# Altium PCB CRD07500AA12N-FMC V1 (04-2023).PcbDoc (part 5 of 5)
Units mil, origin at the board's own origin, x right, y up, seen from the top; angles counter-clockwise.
Board outline 8000 x 8000 mil, 4 copper layers (Top Layer, Layer 1, Layer 2, Bottom Layer), stack 107.988 mil thick; 393 components, 213 nets, 1142 pads, 380 vias.
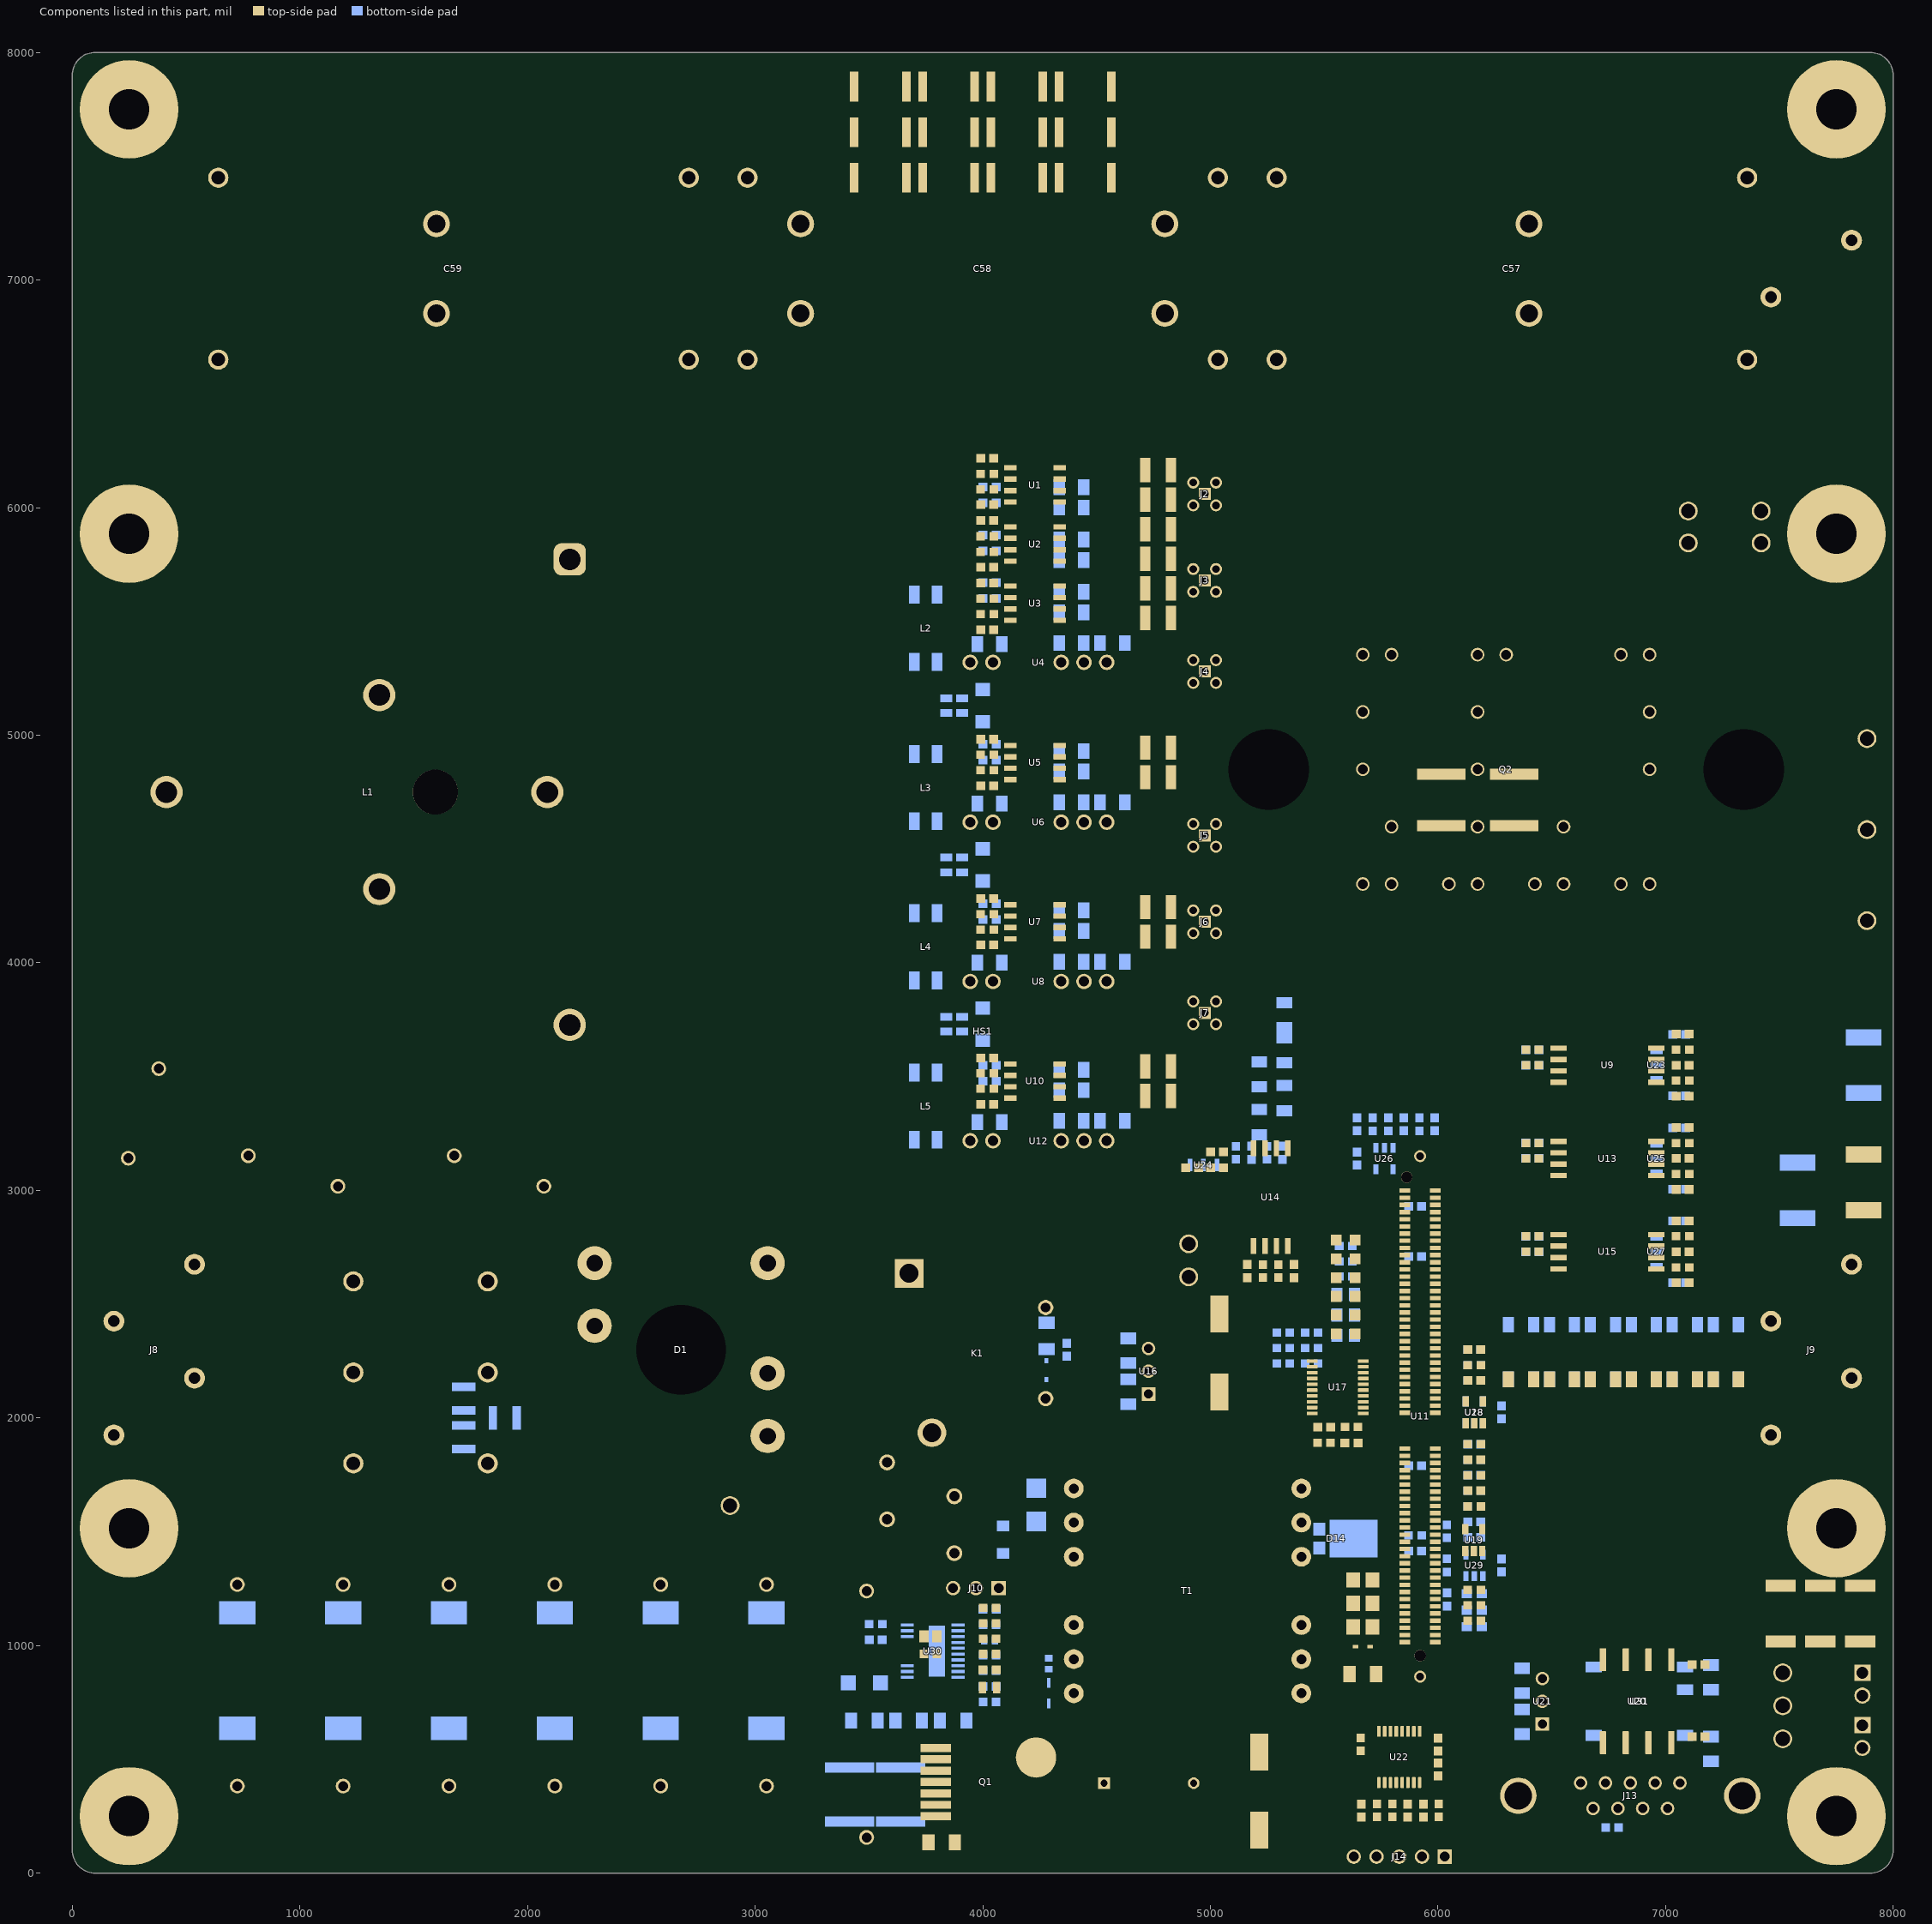
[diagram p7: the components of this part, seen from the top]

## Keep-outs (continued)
Layer 1:
  lines w10: 95,2400 ccw(c145,2400) 145,2350 ; 95,2470 cw(c145,2470) 145,2520 ; 315,3495 ccw(c365,3495) 365,3445 ; 315,3565 cw(c365,3565) 365,3615 ; 450,2140 ccw(c500,2140) 500,2090 ; 450,2210 cw(c500,2210) 500,2260 ; 450,2660 ccw(c500,2660) 500,2610 ; 450,2730 cw(c500,2730) 500,2780 ; 665,374.17 ccw(c715,374.17) 715,324.17 ; 665,389.17 cw(c715,389.17) 715,439.17 ; 1100,1240 ccw(c1150,1240) 1150,1190 ; 1230,1190 ccw(c1230,1240) 1280,1240 ; 1260,4260 ccw(c1310,4260) 1310,4210 ; 1260,4380 cw(c1310,4380) 1310,4430 ; 1270,1715 ccw(c1270,1765) 1320,1765 ; 1270,1885 cw(c1270,1835) 1320,1835 ; 1270,2115 ccw(c1270,2165) 1320,2165 ; 1270,2285 cw(c1270,2235) 1320,2235 ; 1270,2515 ccw(c1270,2565) 1320,2565 ; 1270,2685 cw(c1270,2635) 1320,2635 ; 1385,5270 cw(c1385,5220) 1435,5220 ; 1665,325 ccw(c1665,375) 1715,375 ; 1665,440 cw(c1665,390) 1715,390 ; 1735,2165 ccw(c1785,2165) 1785,2115 ; 1735,2205 cw(c1785,2205) 1785,2255 ; 1754.29,2525 ccw(c1789.64,2560.36) 1825,2525 ; 1864.36,2561.64 ccw(c1829,2597) 1864.36,2632.36 ; 1990,4805 cw(c2040,4805) 2040,4855 ; 2340,2320 ccw(c2340,2370) 2390,2370 ; 2340,2480 cw(c2340,2430) 2390,2430 ; 2960,1255 ccw(c3010,1255) 3010,1205 ; 2960,2165 ccw(c3010,2165) 3010,2115 ; 3090,1205 ccw(c3090,1255) 3140,1255 ; 3125,2115 ccw(c3125,2165) 3175,2165 ; 3210,2595 cw(c3210,2545) 3260,2545 ; 3430,365 ccw(c3480,365) 3480,315 ; 3430,1255 cw(c3480,1255) 3480,1305 ; 3515,2695 cw(c3565,2695) 3565,2745 ; 3648,95 ccw(c3698,95) 3698,45 ; 4110,6245 cw(c4110,6195) 4160,6195 ; 4180,1760 cw(c4180,1710) 4230,1710 ; 4225,2075 ccw(c4275,2075) 4275,2025 ; 4230,1540 ccw(c4280,1540) 4280,1490 ; 4305,6175 cw(c4355,6175) 4355,6225 ; 4415,1492 cw(c4415,1442) 4465,1442 ; 4420,45 ccw(c4420,95) 4470,95 ; 4465,495 ccw(c4515,495) 4515,445 ; 4470,295 cw(c4520,295) 4520,345 ccw(c4520,395) 4570,395 ccw(c4520,395) 4520,445 ; 4945,345 cw(c4945,395) 4895,395 cw(c4945,395) 4945,445 ; 5105,6225 cw(c5105,6175) 5155,6175 ; 5110,345 cw(c5110,295) 5160,295 ; 5110,445 ccw(c5110,495) 5160,495 ; 5160,95 ccw(c5210,95) 5210,45 ; 5160,600 cw(c5210,600) 5210,650 ; 5285,650 ccw(c5285,700) 5335,700 ; 5285,2025 cw(c5285,1975) 5335,1975 ; 5385,5640 ccw(c5435,5640) 5435,5590 ; 5385,5660 cw(c5435,5660) 5435,5710 ; 5570,2885 ccw(c5570,2935) 5620,2935 ; 5620,3335 cw(c5670,3335) 5670,3385 ; 6015,3385 ccw(c6015,3435) 6065,3435 ; 6065,3620 cw(c6115,3620) 6115,3670 ; 6115,45 ccw(c6115,95) 6165,95 ; 6165,530 cw(c6215,530) 6215,580 ; 6175,4385 cw(c6175,4335) 6225,4335 ; 6290,295 ccw(c6340,295) 6340,245 ; 6290,395 cw(c6340,395) 6340,445 ; 6340,1125 ccw(c6390,1125) 6390,1075 ; 6340,2550 cw(c6390,2550) 6390,2600 ; 6355,4020 ccw(c6355,4040) 6375,4040 ; 6355,4080 cw(c6355,4060) 6375,4060 ; 6450,580 ccw(c6450,630) 6500,630 ; 6500,810 cw(c6550,810) 6550,860 ; 6525,2600 ccw(c6525,2650) 6575,2650 ; 6525,3670 cw(c6525,3620) 6575,3620 ; 6550,4385 cw(c6550,4335) 6600,4335 ; 6590,445 ccw(c6590,495) 6640,495 ; 6610.55,3959.71 ccw(c6660.36,3955.36) 6625,3920 ; 6640,585 cw(c6690,585) 6690,635 ; 6900,4005 ccw(c6930,4005) 6930,3975 ; 6900,4050 cw(c6930,4050) 6930,4080 ; 6915,4385 cw(c6915,4335) 6965,4335 ; 6925,5500 cw(c6925,5450) 6975,5450 ; 6997,860 cw(c6997,810) 7047,810 ; 7045,825 ccw(c7095,825) 7095,775 ; 7148.79,4008.79 cw(c7170,4030) 7148.79,4051.21 ; 7178.79,4081.21 cw(c7200,4060) 7221.21,4081.21 ; 7190,635 cw(c7190,585) 7240,585 ; 7190,775 ccw(c7190,825) 7240,825 ; 7240,495 ccw(c7290,495) 7290,445 ; 7240,815 cw(c7290,815) 7290,865 ; 7350,245 ccw(c7350,295) 7400,295 ; 7350,445 cw(c7350,395) 7400,395 ; 7410,1245 ccw(c7460,1245) 7460,1195 ; 7410,1950 cw(c7460,1950) 7460,2000 ; 7415,860 cw(c7415,810) 7465,810 ; 7465,555 ccw(c7515,555) 7515,505 ; 7570,3200 ccw(c7620,3200) 7620,3150 ; 7700,3150 ccw(c7700,3200) 7750,3200 ; 7900,505 ccw(c7900,555) 7950,555 ; 7900,1075 cw(c7900,1025) 7950,1025 ; 7900,1195 ccw(c7900,1245) 7950,1245 ; 7900,2000 cw(c7900,1950) 7950,1950
Layer 2:
  region: 6463.94,5460 6408.94,5460 6408.94,5245 6463.94,5245
  region: 6278.94,4745 6068.94,4745 6068.94,4690 6278.94,4690
  region: 5960,5460 5905,5460 5905,5245 5960,5245
  region: 5775,4745 5565,4745 5565,4690 5775,4690
  rectangle: 6825,4690 7035,4745
  rectangle: 6640,5245 6695,5460
  region: 6069.93,5515 6013.94,5459.01 6013.94,5190 6013.94,4955 6013.94,4745 6334.02,4745 6334.02,4955 6334.02,5190 6408.94,5190 6408.94,5515
  region: 5566,5515 5510,5459.01 5510,5190 5510,4955 5510,4745 5830.08,4745 5830.08,4955 5830.08,5190 5905,5190 5905,5515
  region: 7034,5515 7090,5459.01 7090,5190 7090,4955 7090,4745 6769.92,4745 6769.92,4955 6769.92,5190 6695,5190 6695,5515
  lines w10: 165,3100 ccw(c215,3100) 215,3050 ; 165,3185 cw(c215,3185) 215,3235 ; 205,4845 cw(c255,4845) 255,4895 ; 530,4895 cw(c530,4845) 580,4845 ; 594.21,6215 ccw(c644.21,6215) 644.21,6165 ; 595,6430.79 cw(c645,6430.79) 645,6480.79 ; 595,6870.79 ccw(c645,6870.79) 645,6820.79 ; 595,7230 cw(c645,7230) 645,7280 ; 595,7670 ccw(c645,7670) 645,7620 ; 595,7875 cw(c645,7875) 645,7925 ; 635,1110 ccw(c685,1110) 685,1060 ; 635,1720 cw(c685,1720) 685,1770 ; 650,3235 ccw(c650,3285) 700,3285 ; 700,1770 ccw(c700,1820) 750,1820 ; 700,3050 cw(c700,3000) 750,3000 ; 765,1060 ccw(c765,1110) 815,1110 ; 815,1465 cw(c865,1465) 865,1515 ; 1100,3025 ccw(c1150,3025) 1150,2975 ; 1100,3070 cw(c1150,3070) 1150,3120 ; 1440,2975 cw(c1440,2925) 1490,2925 ; 1440,3120 ccw(c1440,3170) 1490,3170 ; 1490,2165 ccw(c1540,2165) 1540,2115 ; 1565,1110 ccw(c1615,1110) 1615,1060 ; 1610,1665 ccw(c1610,1715) 1660,1715 ; 1660,1805 cw(c1710,1805) 1710,1855 ; 1680,2305 ccw(c1730,2305) 1730,2255 ; 1695,1060 ccw(c1695,1110) 1745,1110 ; 1825,2255 cw(c1825,2205) 1875,2205 ; 1830,1515 ccw(c1830,1565) 1880,1565 ; 1830,1855 cw(c1830,1805) 1880,1805 ; 2040,5910 cw(c2090,5910) 2090,5960 ; 2190,2655 ccw(c2240,2655) 2240,2605 ; 2235,3830 cw(c2235,3780) 2285,3780 ; 2540,5960 cw(c2540,5910) 2590,5910 ; 2730,6165 cw(c2730,6115) 2780,6115 ; 2805,2605 ccw(c2805,2655) 2855,2655 ; 2845,6770 3060,6975 ; 2880,7305 3110,7125 ; 3075,6520 3305,6700 ; 3095,7555 3310,7350 ; 3210,140 ccw(c3260,140) 3260,90 ; 3435,330 ccw(c3485,330) 3485,280 ; 3570,90 ccw(c3570,140) 3620,140 ; 3570,280 cw(c3570,230) 3620,230 ; 4225,2075 ccw(c4275,2075) 4275,2025 ; 4405,1600 ccw(c4405,1650) 4455,1650 ; 4405,1790 cw(c4405,1740) 4455,1740 ; 5015,2885 cw(c5015,2835) 5065,2835 cw(c5115,2835) 5115,2885 ; 5065,2620 ccw(c5115,2620) 5115,2570 ; 5130.79,6365 cw(c5130.79,6315) 5180.79,6315 ; 5160,95 ccw(c5210,95) 5210,45 ; 5160,600 cw(c5210,600) 5210,650 ; 5180,5107 ccw(c5230,5107) 5230,5057 ; 5285,650 ccw(c5285,700) 5335,700 ; 5285,2025 cw(c5285,1975) 5335,1975 ; 5400,2570 ccw(c5400,2620) 5450,2620 ; 5450,2740 cw(c5500,2740) 5500,2790 ; 5465,4610 ccw(c5515,4610) 5515,4560 ; 5515,4745 ccw(c5565,4745) 5565,4695 ; 5515,5460 cw(c5565,5460) 5565,5510 ; 5570,2885 ccw(c5570,2935) 5620,2935 ; 5620,3335 cw(c5670,3335) 5670,3385 ; 5735,2790 ccw(c5735,2840) 5785,2840 ; 5775,4695 ccw(c5775,4745) 5825,4745 ; 5785,3015 cw(c5835,3015) 5835,3065 ; 5825,5145 cw(c5875,5145) 5875,5195 ; 5905,5195 ccw(c5905,5245) 5955,5245 ; 5905,5510 cw(c5905,5460) 5955,5460 ; 6015,3065 cw(c6015,3015) 6065,3015 ; 6015,3385 ccw(c6015,3435) 6065,3435 ; 6018.94,4745 ccw(c6068.94,4745) 6068.94,4695 ; 6018.94,5460 cw(c6068.94,5460) 6068.94,5510 ; 6020,1005 ccw(c6070,1005) 6070,955 ; 6020,1010 ccw(c6070,1010) 6070,960 ; 6065,3620 cw(c6115,3620) 6115,3670 ; 6115,45 ccw(c6115,95) 6165,95 ; 6165,530 cw(c6215,530) 6215,580 ; 6278.94,4695 ccw(c6278.94,4745) 6328.94,4745 ; 6290,960 ccw(c6290,1010) 6340,1010 ; 6295,955 ccw(c6295,1005) 6345,1005 ; 6328.94,5145 cw(c6378.94,5145) 6378.94,5195 ; 6340,2550 cw(c6390,2550) 6390,2600 ; 6345,1025 cw(c6395,1025) 6395,1075 ; 6408.94,5195 ccw(c6408.94,5245) 6458.94,5245 ; 6408.94,5510 cw(c6408.94,5460) 6458.94,5460 ; 6440,295 ccw(c6490,295) 6490,245 ; 6440,395 cw(c6490,395) 6490,445 ; 6450,580 ccw(c6450,630) 6500,630 ; 6525,2600 ccw(c6525,2650) 6575,2650 ; 6525,3670 cw(c6525,3620) 6575,3620 ; 6640,585 cw(c6690,585) 6690,635 ; 6645,5245 ccw(c6695,5245) 6695,5195 ; 6645,5460 cw(c6695,5460) 6695,5510 ; 6725,5195 cw(c6725,5145) 6775,5145 ; 6775,4745 ccw(c6825,4745) 6825,4695 ; 6997,860 cw(c6997,810) 7047,810 ; 7035,4695 ccw(c7035,4745) 7085,4745 ; 7035,5510 cw(c7035,5460) 7085,5460 ; 7045,825 ccw(c7095,825) 7095,775 ; 7085,4560 ccw(c7085,4610) 7135,4610 ; 7190,245 ccw(c7190,295) 7240,295 ; 7190,635 cw(c7190,585) 7240,585 ; 7190,775 ccw(c7190,825) 7240,825 ; 7240,815 cw(c7290,815) 7290,865 ; 7240,5715 ccw(c7290,5715) 7290,5665 ; 7240,6105 cw(c7290,6105) 7290,6155 ; 7320,7925 cw(c7320,7875) 7370,7875 ; 7370,7560 ccw(c7420,7560) 7420,7510 ; 7410,1245 ccw(c7460,1245) 7460,1195 ; 7410,1950 cw(c7460,1950) 7460,2000 ; 7415,860 cw(c7415,810) 7465,810 ; 7420,5057 ccw(c7420,5107) 7470,5107 ; 7420,5665 cw(c7420,5615) 7470,5615 ; 7465,555 ccw(c7515,555) 7515,505 ; 7480,6155 ccw(c7480,6205) 7530,6205 ; 7480,7510 cw(c7480,7460) 7530,7460 ; 7900,505 ccw(c7900,555) 7950,555 ; 7900,1195 ccw(c7900,1245) 7950,1245 ; 7900,2000 cw(c7900,1950) 7950,1950
  lines w100: 2885,6735 3100,6940 ; 2915,7345 3145,7165 ; 3040,6560 3270,6740 ; 3055,7520 3270,7315
Bottom Layer:
  region: 7262,5995 7242,5995 7242,5820 7262,5820
  rectangle: 6918,5820 6938,5995
  lines w10: 20,595 ccw(c70,595) 70,545 ; 20,1930 cw(c70,1930) 70,1980 ; 165,3100 ccw(c215,3100) 215,3050 ; 165,3185 cw(c215,3185) 215,3235 ; 205,4845 cw(c255,4845) 255,4895 ; 395,775 ccw(c445,775) 445,725 ; 420,1980 cw(c420,1930) 470,1930 ; 530,4895 cw(c530,4845) 580,4845 ; 530,6215 ccw(c580,6215) 580,6165 ; 530,7875 cw(c580,7875) 580,7925 ; 635,1110 ccw(c685,1110) 685,1060 ; 635,1720 cw(c685,1720) 685,1770 ; 650,3235 ccw(c650,3285) 700,3285 ; 700,1770 ccw(c700,1820) 750,1820 ; 700,3050 cw(c700,3000) 750,3000 ; 765,1060 ccw(c765,1110) 815,1110 ; 815,1465 cw(c865,1465) 865,1515 ; 1100,1110 ccw(c1150,1110) 1150,1060 ; 1100,1285 cw(c1150,1285) 1150,1335 ; 1100,3025 ccw(c1150,3025) 1150,2975 ; 1100,3070 cw(c1150,3070) 1150,3120 ; 1230,1060 ccw(c1230,1110) 1280,1110 ; 1230,1335 cw(c1230,1285) 1280,1285 ; 1440,2975 cw(c1440,2925) 1490,2925 ; 1440,3120 ccw(c1440,3170) 1490,3170 ; 1465,1965 ccw(c1490,1965) 1490,1940 ; 1465,1975 cw(c1490,1975) 1490,2000 ; 1490,2165 ccw(c1540,2165) 1540,2115 ; 1565,1110 ccw(c1615,1110) 1615,1060 ; 1610,1665 ccw(c1610,1715) 1660,1715 ; 1680,2305 ccw(c1730,2305) 1730,2255 ; 1695,1060 ccw(c1695,1110) 1745,1110 ; 1825,2255 cw(c1825,2205) 1875,2205 ; 1830,1515 ccw(c1830,1565) 1880,1565 ; 1830,1855 cw(c1830,1805) 1880,1805 ; 2030,1110 ccw(c2080,1110) 2080,1060 ; 2040,5910 cw(c2090,5910) 2090,5960 ; 2160,1060 ccw(c2160,1110) 2210,1110 ; 2200,2430 cw(c2250,2430) 2250,2480 ; 2235,3830 cw(c2235,3780) 2285,3780 ; 2340,2480 cw(c2340,2430) 2390,2430 ; 2495,1110 ccw(c2545,1110) 2545,1060 ; 2540,5960 cw(c2540,5910) 2590,5910 ; 2555,2596 ccw(c2605,2596) 2605,2546 ; 2625,1060 ccw(c2625,1110) 2675,1110 ; 2730,6165 cw(c2730,6115) 2780,6115 ; 2894.68,2413.87 ccw(c2940,2435) 2940,2385 ; 2960,1110 ccw(c3010,1110) 3010,1060 ; 2960,1285 cw(c3010,1285) 3010,1335 ; 3090,1060 ccw(c3090,1110) 3140,1110 ; 3090,1335 cw(c3090,1285) 3140,1285 ; 3095,545 ccw(c3095,595) 3145,595 ; 3095,725 cw(c3095,675) 3145,675 ; 3100,2095 ccw(c3100,2145) 3150,2145 ; 3100,2295 cw(c3100,2245) 3150,2245 ; 3215,2385 cw(c3215,2335) 3265,2335 ; 3265,1250 ccw(c3315,1250) 3315,1200 ; 3300,170 ccw(c3350,170) 3350,120 ; 3325,675 ccw(c3375,675) 3375,625 ; 3325,830 cw(c3375,830) 3375,880 ; 3400,880 cw(c3400,830) 3450,830 ; 3485,1200 ccw(c3485,1250) 3535,1250 ; 3485,2795 ccw(c3535,2795) 3535,2745 ; 3535,1460 cw(c3585,1460) 3585,1510 ccw(c3585,1560) 3635,1560 ; 3535,1650 ccw(c3585,1650) 3585,1600 cw(c3585,1550) 3635,1550 ; 3535,2450 cw(c3585,2450) 3585,2500 ; 3705,120 ccw(c3705,170) 3755,170 ; 3719,2500 ccw(c3719,2550) 3769,2550 ; 3720,2744 cw(c3720,2694) 3770,2694 ; 3820,1405 ccw(c3870,1405) 3870,1355 ; 3820,1655 cw(c3870,1655) 3870,1705 ; 3880,1355 ccw(c3880,1405) 3930,1405 ; 3880,1705 cw(c3880,1655) 3930,1655 ; 4225,2075 ccw(c4275,2075) 4275,2025 ; 4687.5,7347.5 4902.5,7552.5 ; 4690,6705 4920,6525 ; 4890,7125 5120,7305 ; 4935,6980 5150,6775 ; 5005,6195 cw(c5005,6145) 5055,6145 ; 5045,6310 cw(c5045,6260) 5095,6260 ; 5050,2885 cw(c5050,2835) 5100,2835 ; 5095,5128 ccw(c5145,5128) 5145,5078 ; 5100,2210 ccw(c5150,2210) 5150,2160 ; 5100,2450 cw(c5150,2450) 5150,2500 ; 5100,2630 ccw(c5150,2630) 5150,2580 ; 5160,95 ccw(c5210,95) 5210,45 ; 5160,600 cw(c5210,600) 5210,650 ; 5285,650 ccw(c5285,700) 5335,700 ; 5285,2025 cw(c5285,1975) 5335,1975 ; 5335,1285 cw(c5385,1285) 5385,1335 cw(c5385,1385) 5335,1385 ; 5335,1555 cw(c5385,1555) 5385,1605 cw(c5385,1655) 5335,1655 ; 5375,5660 cw(c5425,5660) 5425,5710 ; 5460,1335 ccw(c5460,1385) 5510,1385 ; 5460,1605 cw(c5460,1555) 5510,1555 ; 5485,4805 ccw(c5535,4805) 5535,4755 ; 5500,5710 cw(c5500,5660) 5550,5660 ; 5580,2160 cw(c5580,2110) 5630,2110 ; 5630,1650 ccw(c5680,1650) 5680,1600 ; 5685,5025 ccw(c5685,5075) 5735,5075 ; 5685,5230 cw(c5685,5180) 5735,5180 ; 5690,1600 cw(c5690,1550) 5740,1550 ; 5740,1060 ccw(c5790,1060) 5790,1010 ; 6005,4215 ccw(c6055,4215) 6055,4165 ; 6115,45 ccw(c6115,95) 6165,95 ; 6165,530 cw(c6215,530) 6215,580 ; 6175,4385 cw(c6175,4335) 6225,4335 ; 6225,4275 ccw(c6275,4275) 6275,4225 ; 6290,295 ccw(c6340,295) 6340,245 ; 6290,395 cw(c6340,395) 6340,445 ; 6295,4020 cw(c6295,4050) 6265,4050 cw(c6295,4050) 6295,4080 ; 6450,580 ccw(c6450,630) 6500,630 ; 6590,445 ccw(c6590,495) 6640,495 ; 6870,4020 cw(c6870,3990) 6900,3990 ; 6900,3995 ccw(c6920,3995) 6920,3975 ; 6920,1025 cw(c6970,1025) 6970,1075 ; 6945,4080 cw(c6945,4050) 6975,4050 ; 6955,3975 ccw(c6955,3995) 6975,3995 ; 7066,4755 ccw(c7066,4805) 7116,4805 ; 7177.14,3982.14 ccw(c7212.5,4017.5) 7247.86,3982.14 ; 7190,635 cw(c7190,585) 7240,585 ; 7240,495 ccw(c7290,495) 7290,445 ; 7250.47,3984.64 ccw(c7215.12,4020) 7250.47,4055.36 ; 7268.02,6793.8 ccw(c7243.02,6837.1) 7290,6820 ; 7290,7045 cw(c7340,7045) 7340,7095 ; 7350,245 ccw(c7350,295) 7400,295 ; 7350,445 cw(c7350,395) 7400,395 ; 7410,1245 ccw(c7460,1245) 7460,1195 ; 7410,1950 cw(c7460,1950) 7460,2000 ; 7420,5077 ccw(c7420,5127) 7470,5127 ; 7420,6481 cw(c7420,6431) 7470,6431 ; 7420,7619 ccw(c7420,7669) 7470,7669 ; 7420,7925 cw(c7420,7875) 7470,7875 ; 7465,555 ccw(c7515,555) 7515,505 ; 7570,5270 cw(c7620,5270) 7620,5320 ; 7730,2160 ccw(c7780,2160) 7780,2110 ; 7765,2660 ccw(c7815,2660) 7815,2610 ; 7830,7095 ccw(c7830,7145) 7880,7145 ; 7830,7280 cw(c7830,7230) 7880,7230 ; 7855,2110 ccw(c7855,2160) 7905,2160 ; 7900,505 ccw(c7900,555) 7950,555 ; 7900,1075 cw(c7900,1025) 7950,1025 ; 7900,1195 ccw(c7900,1245) 7950,1245 ; 7900,2000 cw(c7900,1950) 7950,1950 ; 7900,5320 cw(c7900,5270) 7950,5270 ; 7925,2610 ccw(c7925,2660) 7975,2660
  lines w100: 4725,6745 4955,6565 ; 4727.5,7312.5 4942.5,7517.5 ; 4855,7165 5085,7345 ; 4895,6945 5110,6740

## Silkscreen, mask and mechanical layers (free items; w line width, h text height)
Top Overlay:
  drawing of 52 lines, arcs and shapes, not listed
  text "DC-" at 7073.42,7125 h100
  text "DC+" at 7073.42,6870 h100
  text "7.5kW WolfPACK FM3 Six-Pack Motor Drive / PN CRD07500AA12N-FMC, V1 04/2023" at 2163.26,6255 h95
  text "H" at 831.25,6231.88 h900
  text "H" at 6531.25,6231.88 h900
  text "(ROFF)" at 4488.23,6126 h35
  text "(RON)" at 4523.21,5996 h35
  text "(ROFF)" at 4488.23,5866 h35
  text "U_L / (G2)" at 4913.6,5865 h35
  text "(RON)" at 4523.21,5736 h35
  text "DC+" at 7020.03,5705 h60
  text "DC-" at 7340.03,5705 h60
  text "(ROFF)" at 4488.23,5606 h35
  text "V_L / (G4)" at 4913.6,5485 h35
  text "(RON)" at 4523.21,5476 h35
  text "W_L / (G6)" at 4913.6,5085 h35
  text "U" at 7708.35,4945 h100
  text "(ROFF)" at 4488.23,4906 h35
  text "(RON)" at 4523.21,4776 h35
  text "V" at 7708.35,4545 h100
  text "W_H / (G5)" at 4913.6,4365 h35
  text "(ROFF)" at 4488.23,4206 h35
  text "W" at 7708.35,4145 h100
  text "(RON)" at 4523.21,4076 h35
  text "V_H / (G3)" at 4913.6,3985 h35
  text "U_H / (G1)" at 4913.6,3585 h35
  text "(ROFF)" at 4488.23,3506 h35
  text "(RON)" at 4523.21,3376 h35
  text "OUTPUTS" at 7560,2820 h125 r90
  text "+12V" at 4605.07,2735 h60
  text "INPUTS" at 795,2643.64 h125 r270
  text "A" at 670,2625 h100
  text "U" at 7273.35,2625 h100
  text "GND" at 4655.05,2590 h60
  text "+12V" at 5270.07,2504 h60
  text "+5V" at 5320.05,2422 h60
  text "B" at 670,2375 h100
  text "V" at 7273.35,2370 h100
  text "+3.3" at 5270.07,2340 h60
  text "C" at 670,2125 h100
  text "W" at 7273.35,2010 h100
  text "g" at 639.18,1741.09 h310
  text "g" at 7154.18,1741.09 h310
  text "BRIDGE-" at 2695.06,1475 h60
  text "EN" at 4174,1215.84 h35 r90
  text "DIS" at 3797.51,1204.51 h35 r90
  text "+" at 7680.01,905 h60
  text "GND" at 7265.05,850 h60
  text "-" at 7729.99,850.01 h60 r90
  text "+3.3V" at 7155.09,705 h60
  text "FAN" at 7720,635.05 h60 r90
  text "+5V" at 7265.05,560 h60
  text "+" at 7680.01,535 h60
  text "-" at 7729.99,480.01 h60 r90
  text "5" at 5460.67,161 h35
  text "GND" at 5523.35,161 h35
  text "+5V" at 5653.35,161 h35
  text "1I" at 5809.59,161 h35
  text "1B" at 5938.76,161 h35
  text "1A" at 6068.76,161 h35
  text "1" at 6176,161 h35
Bottom Overlay:
  lines w10: 3785,3730 3817.36,3730 ; 3785,4430 3817.36,4430 ; 3785,5130 3817.36,5130 ; 5445,2190 5445,2206.3 ; 6220,1285 6240,1265 6385,1265 ; 3665,3650 3785,3650 3785,3810 3665,3810 3665,3650 ; 3665,4350 3785,4350 3785,4510 3665,4510 3665,4350 ; 3665,5050 3785,5050 3785,5210 3665,5210 3665,5050 ; 5370,2020 5520,2020 5520,2190 5370,2190 5370,2020
Board Outline:
  the board outline again, w10
Drill Drawing:
  drawing of 191 lines, arcs and shapes, not listed
  text "THESE HOLES (1.10MM +/- 0.05MM) ARE FOR PRESS-FIT PART. USE 47.2MIL +/- 1MIL DRILLED HOLES. COPPER THICKNESS IN HOLE 25-50UM." at 250,12130 h100
  text "w" at 34.31,12114.72 h200
  text "Symbol" at 109.62,11935 h72
  text "Count" at 615.49,11935 h72
  text "Hole Size" at 1215.34,11935 h72
  text "Plated" at 2365,11935 h72
  text "Hole Type" at 2870.88,11935 h72
  text "Drill Layer Pair" at 3604.68,11935 h72
  text "Via/Pad" at 5104.23,11935 h72
  text "Pad Shape" at 5694.08,11935 h72
  text "Hole Tolerance (+)" at 6439.88,11935 h72
  text "Hole Tolerance (-)" at 7773.48,11935 h72
  text "Hole Length" at 9107.09,11935 h72
  text "Routed Path Length" at 9972.85,11935 h72
  text "367" at 615.49,11785 h60
  text "0.33mm (13.00mil)" at 1215.34,11785 h60
  text "PTH" at 2365,11785 h60
  text "Round" at 2870.88,11785 h60
  text "Top Layer - Bottom Layer" at 3604.68,11785 h60
  text "Via" at 5104.23,11785 h60
  text "Rounded" at 5694.08,11785 h60
  text "0.08mm (3.00mil)" at 6439.88,11785 h60
  text "0.08mm (3.00mil)" at 7773.48,11785 h60
  text "-" at 9107.09,11785 h60
  text "-" at 9972.85,11785 h60
  text "A" at 80.53,11775.01 h66.67
  text "13" at 615.49,11635 h60
  text "0.71mm (28.00mil)" at 1215.34,11635 h60
  text "PTH" at 2365,11635 h60
  text "Round" at 2870.88,11635 h60
  text "Top Layer - Bottom Layer" at 3604.68,11635 h60
  text "Via" at 5104.23,11635 h60
  text "Rounded" at 5694.08,11635 h60
  text "0.08mm (3.00mil)" at 6439.88,11635 h60
  text "0.08mm (3.00mil)" at 7773.48,11635 h60
  text "-" at 9107.09,11635 h60
  text "-" at 9972.85,11635 h60
  text "2" at 615.49,11485 h60
  text "0.80mm (31.50mil)" at 1215.34,11485 h60
  text "PTH" at 2365,11485 h60
  text "Round" at 2870.88,11485 h60
  text "Top Layer - Bottom Layer" at 3604.68,11485 h60
  text "Pad" at 5104.23,11485 h60
  text "(Mixed)" at 5694.08,11485 h60
  text "0.08mm (3.00mil)" at 6439.88,11485 h60
  text "0.08mm (3.00mil)" at 7773.48,11485 h60
  text "-" at 9107.09,11485 h60
  text "-" at 9972.85,11485 h60
  text "D" at 80.53,11475.01 h66.67
  text "32" at 615.49,11335 h60
  text "0.84mm (33.07mil)" at 1215.34,11335 h60
  text "PTH" at 2365,11335 h60
  text "Round" at 2870.88,11335 h60
  text "Top Layer - Bottom Layer" at 3604.68,11335 h60
  text "Pad" at 5104.23,11335 h60
  text "(Mixed)" at 5694.08,11335 h60
  text "0.08mm (3.00mil)" at 6439.88,11335 h60
  text "0.08mm (3.00mil)" at 7773.48,11335 h60
  text "-" at 9107.09,11335 h60
  text "-" at 9972.85,11335 h60
  text "15" at 615.49,11185 h60
  text "1.00mm (39.37mil)" at 1215.34,11185 h60
  text "PTH" at 2365,11185 h60
  text "Round" at 2870.88,11185 h60
  text "Top Layer - Bottom Layer" at 3604.68,11185 h60
  text "Pad" at 5104.23,11185 h60
  text "(Mixed)" at 5694.08,11185 h60
  text "0.08mm (3.00mil)" at 6439.88,11185 h60
  text "0.08mm (3.00mil)" at 7773.48,11185 h60
  text "-" at 9107.09,11185 h60
  text "-" at 9972.85,11185 h60
  text "23" at 615.49,11035 h60
  text "1.10mm (43.31mil)" at 1215.34,11035 h60
  text "PTH" at 2365,11035 h60
  text "Round" at 2870.88,11035 h60
  text "Top Layer - Bottom Layer" at 3604.68,11035 h60
  text "Pad" at 5104.23,11035 h60
  text "Rounded" at 5694.08,11035 h60
  text "0.05mm (1.97mil)" at 6439.88,11035 h60
  text "0.05mm (1.97mil)" at 7773.48,11035 h60
  text "-" at 9107.09,11035 h60
  text "-" at 9972.85,11035 h60
  text "w" at -180.69,10999.72 h200
  text "42" at 615.49,10885 h60
  text "1.10mm (43.31mil)" at 1215.34,10885 h60
  text "PTH" at 2365,10885 h60
  text "Round" at 2870.88,10885 h60
  text "Top Layer - Bottom Layer" at 3604.68,10885 h60
  text "Pad" at 5104.23,10885 h60
  text "(Mixed)" at 5694.08,10885 h60
  text "0.08mm (3.00mil)" at 6439.88,10885 h60
  text "0.08mm (3.00mil)" at 7773.48,10885 h60
  text "-" at 9107.09,10885 h60
  text "-" at 9972.85,10885 h60
  text "4" at 615.49,10735 h60
  text "1.14mm (45.00mil)" at 1215.34,10735 h60
  text "PTH" at 2365,10735 h60
  text "Round" at 2870.88,10735 h60
  text "Top Layer - Bottom Layer" at 3604.68,10735 h60
  text "Pad" at 5104.23,10735 h60
  text "Rounded" at 5694.08,10735 h60
  text "0.08mm (3.00mil)" at 6439.88,10735 h60
  text "0.08mm (3.00mil)" at 7773.48,10735 h60
  text "-" at 9107.09,10735 h60
  text "-" at 9972.85,10735 h60
  text "20" at 615.49,10585 h60
  text "1.15mm (45.28mil)" at 1215.34,10585 h60
  text "PTH" at 2365,10585 h60
  text "Round" at 2870.88,10585 h60
  text "Top Layer - Bottom Layer" at 3604.68,10585 h60
  text "Pad" at 5104.23,10585 h60
  text "Rounded" at 5694.08,10585 h60
  text "0.08mm (3.00mil)" at 6439.88,10585 h60
  text "0.08mm (3.00mil)" at 7773.48,10585 h60
  text "-" at 9107.09,10585 h60
  text "-" at 9972.85,10585 h60
  text "2" at 615.49,10435 h60
  text "1.27mm (50.00mil)" at 1215.34,10435 h60
  text "NPTH" at 2365,10435 h60
  text "Round" at 2870.88,10435 h60
  text "Top Layer - Bottom Layer" at 3604.68,10435 h60
  text "Pad" at 5104.23,10435 h60
  text "Rounded" at 5694.08,10435 h60
  text "0.08mm (3.00mil)" at 6439.88,10435 h60
  text "0.08mm (3.00mil)" at 7773.48,10435 h60
  text "-" at 9107.09,10435 h60
  text "-" at 9972.85,10435 h60
  text "14" at 615.49,10285 h60
  text "1.30mm (51.18mil)" at 1215.34,10285 h60
  text "PTH" at 2365,10285 h60
  text "Round" at 2870.88,10285 h60
  text "Top Layer - Bottom Layer" at 3604.68,10285 h60
  text "Pad" at 5104.23,10285 h60
  text "(Mixed)" at 5694.08,10285 h60
  text "0.08mm (3.00mil)" at 6439.88,10285 h60
  text "0.08mm (3.00mil)" at 7773.48,10285 h60
  text "-" at 9107.09,10285 h60
  text "-" at 9972.85,10285 h60
  text "18" at 615.49,10135 h60
  text "1.50mm (59.06mil)" at 1215.34,10135 h60
  text "PTH" at 2365,10135 h60
  text "Round" at 2870.88,10135 h60
  text "Top Layer - Bottom Layer" at 3604.68,10135 h60
  text "Pad" at 5104.23,10135 h60
  text "Rounded" at 5694.08,10135 h60
  text "0.08mm (3.00mil)" at 6439.88,10135 h60
  text "0.08mm (3.00mil)" at 7773.48,10135 h60
  text "-" at 9107.09,10135 h60
  text "-" at 9972.85,10135 h60
  text "13" at 615.49,9985 h60
  text "1.60mm (62.99mil)" at 1215.34,9985 h60
  text "PTH" at 2365,9985 h60
  text "Round" at 2870.88,9985 h60
  text "Top Layer - Bottom Layer" at 3604.68,9985 h60
  text "Pad" at 5104.23,9985 h60
  text "Rounded" at 5694.08,9985 h60
  text "0.08mm (3.00mil)" at 6439.88,9985 h60
  text "0.08mm (3.00mil)" at 7773.48,9985 h60
  text "-" at 9107.09,9985 h60
  text "-" at 9972.85,9985 h60
  text "5" at 615.49,9835 h60
  text "1.85mm (72.84mil)" at 1215.34,9835 h60
  text "PTH" at 2365,9835 h60
  text "Round" at 2870.88,9835 h60
  text "Top Layer - Bottom Layer" at 3604.68,9835 h60
  text "Pad" at 5104.23,9835 h60
  text "Rounded" at 5694.08,9835 h60
  text "0.08mm (3.00mil)" at 6439.88,9835 h60
  text "0.08mm (3.00mil)" at 7773.48,9835 h60
  text "-" at 9107.09,9835 h60
  text "-" at 9972.85,9835 h60
  text "B" at 80.53,9825.01 h66.67
  text "8" at 615.49,9685 h60
  text "2.00mm (78.74mil)" at 1215.34,9685 h60
  text "PTH" at 2365,9685 h60
  text "Round" at 2870.88,9685 h60
  text "Top Layer - Bottom Layer" at 3604.68,9685 h60
  text "Pad" at 5104.23,9685 h60
  text "Rounded" at 5694.08,9685 h60
  text "0.08mm (3.00mil)" at 6439.88,9685 h60
  text "0.08mm (3.00mil)" at 7773.48,9685 h60
  text "-" at 9107.09,9685 h60
  text "-" at 9972.85,9685 h60
  text "2" at 615.49,9535 h60
  text "2.10mm (82.68mil)" at 1215.34,9535 h60
  text "PTH" at 2365,9535 h60
  text "Round" at 2870.88,9535 h60
  text "Top Layer - Bottom Layer" at 3604.68,9535 h60
  text "Pad" at 5104.23,9535 h60
  text "(Mixed)" at 5694.08,9535 h60
  text "0.08mm (3.00mil)" at 6439.88,9535 h60
  text "0.08mm (3.00mil)" at 7773.48,9535 h60
  text "-" at 9107.09,9535 h60
  text "-" at 9972.85,9535 h60
  text "6" at 615.49,9385 h60
  text "2.40mm (94.49mil)" at 1215.34,9385 h60
  text "PTH" at 2365,9385 h60
  text "Round" at 2870.88,9385 h60
  text "Top Layer - Bottom Layer" at 3604.68,9385 h60
  text "Pad" at 5104.23,9385 h60
  text "(Mixed)" at 5694.08,9385 h60
  text "0.13mm (5.00mil)" at 6439.88,9385 h60
  text "0.13mm (5.00mil)" at 7773.48,9385 h60
  text "-" at 9107.09,9385 h60
  text "-" at 9972.85,9385 h60
  text "E" at 80.53,9375.01 h66.67
  text "2" at 615.49,9235 h60
  text "3.05mm (120.08mil)" at 1215.34,9235 h60
  text "PTH" at 2365,9235 h60
  text "Round" at 2870.88,9235 h60
  text "Top Layer - Bottom Layer" at 3604.68,9235 h60
  text "Pad" at 5104.23,9235 h60
  text "Rounded" at 5694.08,9235 h60
  text "0.13mm (5.00mil)" at 6439.88,9235 h60
  text "0.13mm (5.00mil)" at 7773.48,9235 h60
  text "-" at 9107.09,9235 h60
  text "-" at 9972.85,9235 h60
  text "G" at 80.53,9225.01 h66.67
  text "8" at 615.49,9085 h60
  text "4.50mm (177.17mil)" at 1215.34,9085 h60
  text "PTH" at 2365,9085 h60
  text "Round" at 2870.88,9085 h60
  text "Top Layer - Bottom Layer" at 3604.68,9085 h60
  text "Pad" at 5104.23,9085 h60
  text "Rounded" at 5694.08,9085 h60
  text "0.13mm (5.00mil)" at 6439.88,9085 h60
  text "0.13mm (5.00mil)" at 7773.48,9085 h60
  text "-" at 9107.09,9085 h60
  text "-" at 9972.85,9085 h60
  text "1" at 615.49,8935 h60
  text "5.00mm (196.85mil)" at 1215.34,8935 h60
  text "NPTH" at 2365,8935 h60
  text "Round" at 2870.88,8935 h60
  text "Top Layer - Bottom Layer" at 3604.68,8935 h60
  text "Pad" at 5104.23,8935 h60
  text "Rounded" at 5694.08,8935 h60
  text "0.13mm (5.00mil)" at 6439.88,8935 h60
  text "0.13mm (5.00mil)" at 7773.48,8935 h60
  text "-" at 9107.09,8935 h60
  text "-" at 9972.85,8935 h60
  text "F" at 80.53,8925.01 h66.67
  text "2" at 615.49,8785 h60
  text "9.00mm (354.33mil)" at 1215.34,8785 h60
  text "NPTH" at 2365,8785 h60
  text "Round" at 2870.88,8785 h60
  text "Top Layer - Bottom Layer" at 3604.68,8785 h60
  text "Pad" at 5104.23,8785 h60
  text "Rounded" at 5694.08,8785 h60
  text "0.13mm (5.00mil)" at 6439.88,8785 h60
  text "0.13mm (5.00mil)" at 7773.48,8785 h60
  text "-" at 9107.09,8785 h60
  text "-" at 9972.85,8785 h60
  text "H" at 80.53,8775.01 h66.67
  text "1" at 615.49,8635 h60
  text "10.00mm (393.70mil)" at 1215.34,8635 h60
  text "NPTH" at 2365,8635 h60
  text "Round" at 2870.88,8635 h60
  text "Top Layer - Bottom Layer" at 3604.68,8635 h60
  text "Pad" at 5104.23,8635 h60
  text "Rounded" at 5694.08,8635 h60
  text "0.13mm (5.00mil)" at 6439.88,8635 h60
  text "0.13mm (5.00mil)" at 7773.48,8635 h60
  text "-" at 9107.09,8635 h60
  text "-" at 9972.85,8635 h60
  text "C" at 80.53,8625.01 h66.67
  text "600 Total" at 615.49,8485 h60

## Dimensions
0,100 to 8000,100 on Drill Drawing
100,0 to 100,8000 on Drill Drawing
